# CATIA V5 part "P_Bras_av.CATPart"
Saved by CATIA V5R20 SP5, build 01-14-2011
Part number: Bras_av
Bounding box of the stored display mesh (mm): x -5 to 5, y 380 to 430, z -23 to 150
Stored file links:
  U:\2A\CFAO\dossier sans titre\P_Bras_av.CATPart
  U:\2A\CFAO\dossier sans titre\Gouvernail.CATProduct
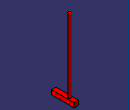
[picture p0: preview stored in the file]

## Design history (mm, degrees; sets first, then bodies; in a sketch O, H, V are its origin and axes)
Set1
  Point1: linked copy from another document
  Point2: linked copy from another document
Body1 (main body)
  Sketch1 on yz-plane, origin (0, 0, 0), H (0, 1, 0), V (0, 0, 1)
    line L1 (380, -13) -> (430, -13)
    line L2 (430, -13) -> (430, -23)
    line L3 (430, -23) -> (380, -23)
    line L4 (380, -23) -> (380, -13)
    reference projected point E1 (430, -10) from Point2
    length L3 = 50
    length L2 = 10
    distance L1 H = 13
    horizontal: L1 H, L3 H
    vertical: L2 V, L4 V
    coincidence: L2 E1
  Pad1 "Extrusion_corps": profile Sketch1, direction (1, 0, 0), length 5, opposite side length 5
  Sketch2 on xy-plane, origin (0, 0, 0), H (1, 0, 0), V (0, 1, 0)
    circle A1 centre (0, 415) radius 3
    point P1 (0, 415)
    reference projected point E1 (0, 415) from Point1
    radius A1 = 3
    coincidence: P1 E1
  Pad2 "Extrusion_axe": profile Sketch2, direction (0, 0, 1), length 150, opposite side length 13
